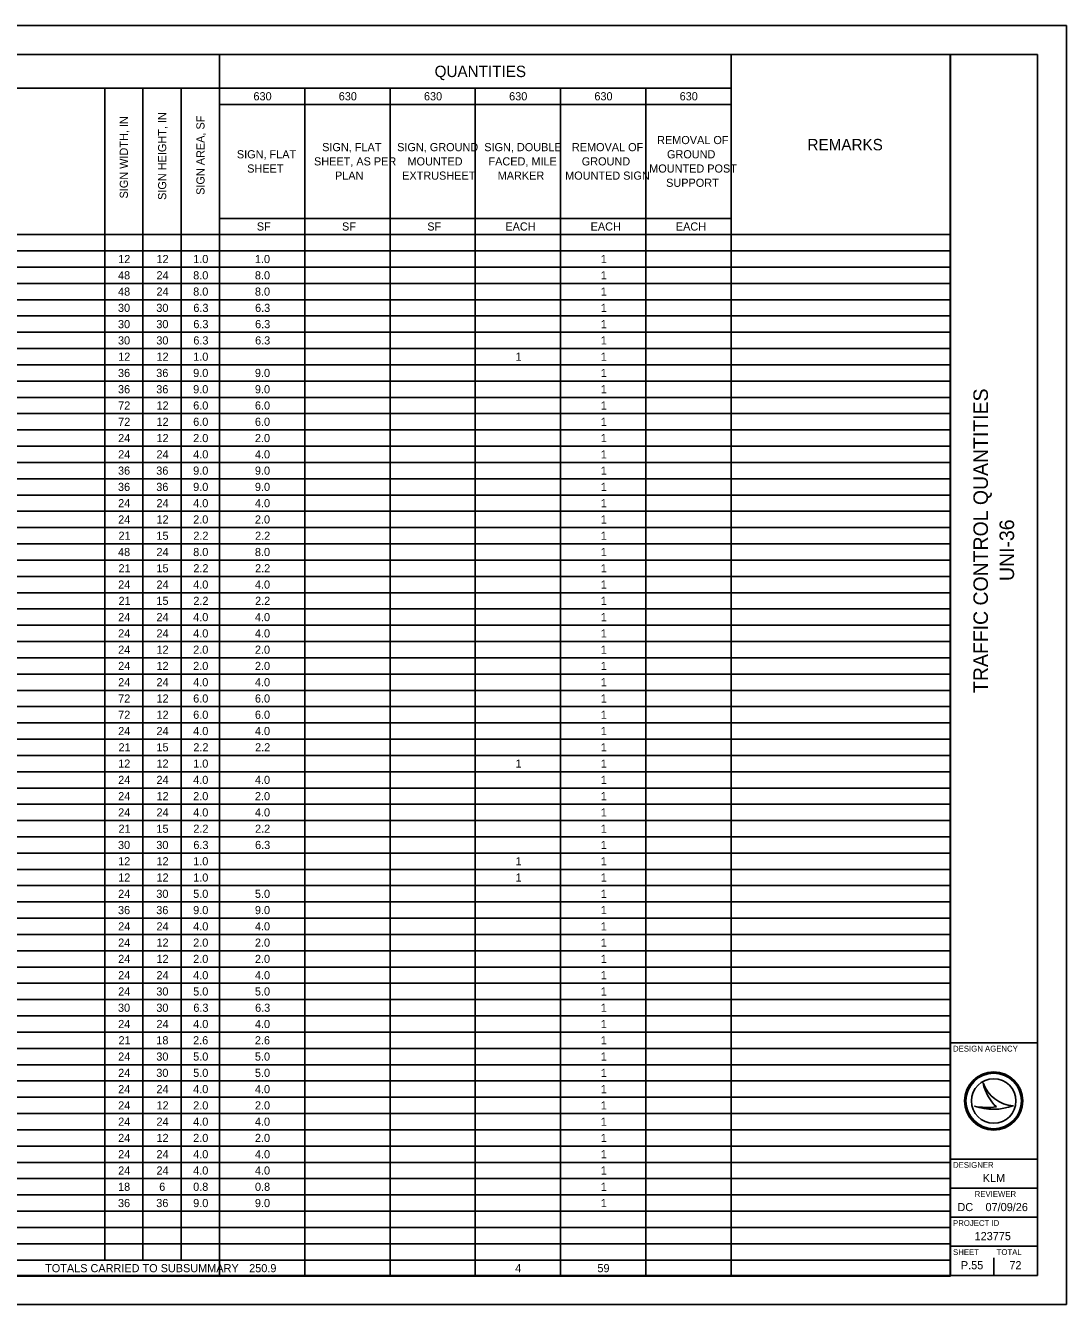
# Model space of a CAD drawing. Extents: x 0 to 34, y 0 to 22.
# Drawn here: x 16.1 to 34, y 0 to 22 of the extents above; entities that cross this region are included whole.
import ezdxf

# ---------------------------------------------------------------- set-up
doc = ezdxf.new("R2010")
doc.units = 0
for name, color, linetype in [('Default', 7, 'Continuous'), ('SH_Border', 7, 'Continuous'), ('SH_Cut_Line', 7, 'Continuous'), ('SH_Data', 7, 'Continuous')]:
    doc.layers.add(name, color=color, linetype=linetype)

msp = doc.modelspace()

# ---------------------------------------------------------------- linework, layer by layer
at = {"layer": 'SH_Border'}
for p, q in [((32, 0.5), (32, 21.5)), ((32, 4.5), (33.5, 4.5)), ((32, 2.5), (33.5, 2.5)), ((32, 2), (33.5, 2)), ((32, 1.5), (33.5, 1.5)), ((32, 1), (33.5, 1))]:
    msp.add_line(p, q, dxfattribs=at)
msp.add_lwpolyline([(1.5, 21.5), (33.5, 21.5), (33.5, 0.5), (1.5, 0.5)], close=True, dxfattribs=at)
at = {"layer": 'SH_Cut_Line'}
msp.add_lwpolyline([(0, 0), (34, 0), (34, 22), (0, 22)], close=True, dxfattribs=at)
at = {"layer": 'SH_Data'}
for p, q in [((1.5, 21.5), (32.004, 21.5)), ((19.436, 21.5), (19.436, 0.484)), ((28.232, 21.5), (28.232, 0.484)), ((32.004, 21.5), (32.004, 0.484)), ((1.5, 20.924), (28.232, 20.924)), ((17.46, 20.924), (17.46, 0.764)), ((18.119, 20.924), (18.119, 0.764)), ((18.778, 20.924), (18.778, 0.764)), ((20.902, 20.924), (20.902, 0.484)), ((22.368, 20.924), (22.368, 0.484)), ((23.834, 20.924), (23.834, 0.484)), ((25.3, 20.924), (25.3, 0.484)), ((26.766, 20.924), (26.766, 0.484)), ((19.436, 20.644), (28.232, 20.644)), ((19.436, 18.684), (28.232, 18.684)), ((1.5, 18.404), (32.004, 18.404)), ((1.5, 18.124), (32.004, 18.124)), ((1.5, 17.844), (32.004, 17.844)), ((1.5, 17.564), (32.004, 17.564)), ((1.5, 17.284), (32.004, 17.284)), ((1.5, 17.004), (32.004, 17.004)), ((1.5, 16.724), (32.004, 16.724)), ((1.5, 16.444), (32.004, 16.444)), ((1.5, 16.164), (32.004, 16.164)), ((1.5, 15.884), (32.004, 15.884)), ((1.5, 15.604), (32.004, 15.604)), ((1.5, 15.324), (32.004, 15.324)), ((1.5, 15.044), (32.004, 15.044)), ((1.5, 14.764), (32.004, 14.764)), ((1.5, 14.484), (32.004, 14.484)), ((1.5, 14.204), (32.004, 14.204)), ((1.5, 13.924), (32.004, 13.924)), ((1.5, 13.644), (32.004, 13.644)), ((1.5, 13.364), (32.004, 13.364)), ((1.5, 13.084), (32.004, 13.084)), ((1.5, 12.804), (32.004, 12.804)), ((1.5, 12.524), (32.004, 12.524)), ((1.5, 12.244), (32.004, 12.244)), ((1.5, 11.964), (32.004, 11.964)), ((1.5, 11.684), (32.004, 11.684)), ((1.5, 11.404), (32.004, 11.404)), ((1.5, 11.124), (32.004, 11.124)), ((1.5, 10.844), (32.004, 10.844)), ((1.5, 10.564), (32.004, 10.564)), ((1.5, 10.284), (32.004, 10.284)), ((1.5, 10.004), (32.004, 10.004)), ((1.5, 9.724), (32.004, 9.724)), ((1.5, 9.444), (32.004, 9.444)), ((1.5, 9.164), (32.004, 9.164)), ((1.5, 8.884), (32.004, 8.884)), ((1.5, 8.604), (32.004, 8.604)), ((1.5, 8.324), (32.004, 8.324)), ((1.5, 8.044), (32.004, 8.044)), ((1.5, 7.764), (32.004, 7.764)), ((1.5, 7.484), (32.004, 7.484)), ((1.5, 7.204), (32.004, 7.204)), ((1.5, 6.924), (32.004, 6.924)), ((1.5, 6.644), (32.004, 6.644)), ((1.5, 6.364), (32.004, 6.364)), ((1.5, 6.084), (32.004, 6.084)), ((1.5, 5.804), (32.004, 5.804)), ((1.5, 5.524), (32.004, 5.524)), ((1.5, 5.244), (32.004, 5.244)), ((1.5, 4.964), (32.004, 4.964)), ((1.5, 4.684), (32.004, 4.684)), ((1.5, 4.404), (32.004, 4.404)), ((1.5, 4.124), (32.004, 4.124)), ((1.5, 3.844), (32.004, 3.844)), ((32.567, 3.81), (32.567, 3.81)), ((1.5, 3.564), (32.004, 3.564)), ((32.417, 3.41), (32.417, 3.41)), ((32.75, 3.5), (32.75, 3.5)), ((33.087, 3.419), (33.087, 3.419)), ((1.5, 3.284), (32.004, 3.284)), ((1.5, 3.004), (32.004, 3.004)), ((1.5, 2.724), (32.004, 2.724)), ((1.5, 2.444), (32.004, 2.444)), ((1.5, 2.164), (32.004, 2.164)), ((1.5, 1.884), (32.004, 1.884)), ((1.5, 1.604), (32.004, 1.604)), ((1.5, 1.324), (32.004, 1.324)), ((1.5, 1.044), (32.004, 1.044)), ((1.5, 0.764), (32.004, 0.764)), ((32.375, 0.675), (32.375, 0.675)), ((32.75, 0.5), (32.75, 0.8)), ((1.5, 0.484), (32.004, 0.484))]:
    msp.add_line(p, q, dxfattribs=at)
for radius in [0.5, 0.477, 0.477, 0.382]:
    msp.add_circle((32.75, 3.5), radius, dxfattribs=at)
for centre, radius, start, end in [((33.116, 3.998), 0.58, 198.9257, 198.9319), ((33.347, 3.97), 0.796, 191.6379, 191.6421), ((33.116, 3.998), 0.58, 198.9319, 267.1657), ((33.347, 3.97), 0.796, 191.6421, 226.0947), ((32.739, 4.37), 1.013, 251.4576, 290.0832), ((32.648, 4.654), 1.266, 259.4964, 259.4995), ((32.739, 4.37), 1.013, 251.4527, 251.4576), ((32.648, 4.654), 1.266, 259.4995, 276.6672)]:
    msp.add_arc(centre, radius, start, end, dxfattribs=at)

# ---------------------------------------------------------------- texts
at = {"layer": 'Default'}
for s, height, p in [('QUANTITIES', 0.196, (23.134, 21.114)), ('630', 0.14, (20.019, 20.714)), ('630', 0.14, (21.485, 20.714)), ('630', 0.14, (22.951, 20.714)), ('630', 0.14, (24.416, 20.714)), ('630', 0.14, (25.882, 20.714)), ('630', 0.14, (27.348, 20.714)), ('REMOVAL OF ', 0.14, (26.961, 19.961)), ('REMARKS', 0.196, (29.547, 19.854)), ('SIGN, FLAT ', 0.14, (19.734, 19.716)), ('SIGN, FLAT ', 0.14, (21.2, 19.839)), ('SIGN, GROUND ', 0.14, (22.49, 19.839)), ('SIGN, DOUBLE ', 0.14, (23.988, 19.839)), ('REMOVAL OF ', 0.14, (25.495, 19.839)), ('GROUND ', 0.14, (27.131, 19.716)), ('SHEET', 0.14, (19.911, 19.471)), ('SHEET, AS PER ', 0.14, (21.06, 19.594)), ('MOUNTED ', 0.14, (22.668, 19.594)), ('FACED, MILE ', 0.14, (24.061, 19.594)), ('GROUND ', 0.14, (25.665, 19.594)), ('MOUNTED POST ', 0.14, (26.825, 19.471)), ('PLAN', 0.14, (21.421, 19.349)), ('EXTRUSHEET', 0.14, (22.576, 19.349)), ('MARKER', 0.14, (24.219, 19.349)), ('MOUNTED SIGN', 0.14, (25.379, 19.349)), ('SUPPORT', 0.14, (27.116, 19.226)), ('SF', 0.14, (20.076, 18.474)), ('SF', 0.14, (21.542, 18.474)), ('SF', 0.14, (23.008, 18.474)), ('EACH', 0.14, (24.351, 18.474)), ('EACH', 0.14, (25.817, 18.474)), ('EACH', 0.14, (27.283, 18.474)), ('12', 0.14, (17.692, 17.914)), ('12', 0.14, (18.351, 17.914)), ('1.0', 0.14, (18.982, 17.914)), ('1.0', 0.14, (20.044, 17.914)), ('1', 0.14, (25.992, 17.914)), ('48', 0.14, (17.69, 17.634)), ('24', 0.14, (18.351, 17.634)), ('8.0', 0.14, (18.982, 17.634)), ('8.0', 0.14, (20.044, 17.634)), ('1', 0.14, (25.992, 17.634)), ('48', 0.14, (17.69, 17.354)), ('24', 0.14, (18.351, 17.354)), ('8.0', 0.14, (18.982, 17.354)), ('8.0', 0.14, (20.044, 17.354)), ('1', 0.14, (25.992, 17.354)), ('30', 0.14, (17.689, 17.074)), ('30', 0.14, (18.348, 17.074)), ('6.3', 0.14, (18.985, 17.074)), ('6.3', 0.14, (20.047, 17.074)), ('1', 0.14, (25.992, 17.074)), ('30', 0.14, (17.689, 16.794)), ('30', 0.14, (18.348, 16.794)), ('6.3', 0.14, (18.985, 16.794)), ('6.3', 0.14, (20.047, 16.794)), ('1', 0.14, (25.992, 16.794)), ('30', 0.14, (17.689, 16.514)), ('30', 0.14, (18.348, 16.514)), ('6.3', 0.14, (18.985, 16.514)), ('6.3', 0.14, (20.047, 16.514)), ('1', 0.14, (25.992, 16.514)), ('12', 0.14, (17.692, 16.234)), ('12', 0.14, (18.351, 16.234)), ('1.0', 0.14, (18.982, 16.234)), ('1', 0.14, (24.526, 16.234)), ('1', 0.14, (25.992, 16.234)), ('36', 0.14, (17.689, 15.954)), ('36', 0.14, (18.347, 15.954)), ('9.0', 0.14, (18.982, 15.954)), ('9.0', 0.14, (20.044, 15.954)), ('1', 0.14, (25.992, 15.954)), ('36', 0.14, (17.689, 15.674)), ('36', 0.14, (18.347, 15.674)), ('9.0', 0.14, (18.982, 15.674)), ('9.0', 0.14, (20.044, 15.674)), ('1', 0.14, (25.992, 15.674)), ('72', 0.14, (17.692, 15.394)), ('12', 0.14, (18.351, 15.394)), ('6.0', 0.14, (18.982, 15.394)), ('6.0', 0.14, (20.044, 15.394)), ('1', 0.14, (25.992, 15.394)), ('72', 0.14, (17.692, 15.114)), ('12', 0.14, (18.351, 15.114)), ('6.0', 0.14, (18.982, 15.114)), ('6.0', 0.14, (20.044, 15.114)), ('1', 0.14, (25.992, 15.114)), ('24', 0.14, (17.692, 14.834)), ('12', 0.14, (18.351, 14.834)), ('2.0', 0.14, (18.982, 14.834)), ('2.0', 0.14, (20.044, 14.834)), ('1', 0.14, (25.992, 14.834)), ('24', 0.14, (17.692, 14.554)), ('24', 0.14, (18.351, 14.554)), ('4.0', 0.14, (18.982, 14.554)), ('4.0', 0.14, (20.044, 14.554)), ('1', 0.14, (25.992, 14.554)), ('36', 0.14, (17.689, 14.274)), ('36', 0.14, (18.347, 14.274)), ('9.0', 0.14, (18.982, 14.274)), ('9.0', 0.14, (20.044, 14.274)), ('1', 0.14, (25.992, 14.274)), ('36', 0.14, (17.689, 13.994)), ('36', 0.14, (18.347, 13.994)), ('9.0', 0.14, (18.982, 13.994)), ('9.0', 0.14, (20.044, 13.994)), ('1', 0.14, (25.992, 13.994)), ('24', 0.14, (17.692, 13.714)), ('24', 0.14, (18.351, 13.714)), ('4.0', 0.14, (18.982, 13.714)), ('4.0', 0.14, (20.044, 13.714)), ('1', 0.14, (25.992, 13.714)), ('24', 0.14, (17.692, 13.434)), ('12', 0.14, (18.351, 13.434)), ('2.0', 0.14, (18.982, 13.434)), ('2.0', 0.14, (20.044, 13.434)), ('1', 0.14, (25.992, 13.434)), ('21', 0.14, (17.698, 13.154)), ('15', 0.14, (18.35, 13.154)), ('2.2', 0.14, (18.985, 13.154)), ('2.2', 0.14, (20.047, 13.154)), ('1', 0.14, (25.992, 13.154)), ('48', 0.14, (17.69, 12.874)), ('24', 0.14, (18.351, 12.874)), ('8.0', 0.14, (18.982, 12.874)), ('8.0', 0.14, (20.044, 12.874)), ('1', 0.14, (25.992, 12.874)), ('21', 0.14, (17.698, 12.594)), ('15', 0.14, (18.35, 12.594)), ('2.2', 0.14, (18.985, 12.594)), ('2.2', 0.14, (20.047, 12.594)), ('1', 0.14, (25.992, 12.594)), ('24', 0.14, (17.692, 12.314)), ('24', 0.14, (18.351, 12.314)), ('4.0', 0.14, (18.982, 12.314)), ('4.0', 0.14, (20.044, 12.314)), ('1', 0.14, (25.992, 12.314)), ('21', 0.14, (17.698, 12.034)), ('15', 0.14, (18.35, 12.034)), ('2.2', 0.14, (18.985, 12.034)), ('2.2', 0.14, (20.047, 12.034)), ('1', 0.14, (25.992, 12.034)), ('24', 0.14, (17.692, 11.754)), ('24', 0.14, (18.351, 11.754)), ('4.0', 0.14, (18.982, 11.754)), ('4.0', 0.14, (20.044, 11.754)), ('1', 0.14, (25.992, 11.754)), ('24', 0.14, (17.692, 11.474)), ('24', 0.14, (18.351, 11.474)), ('4.0', 0.14, (18.982, 11.474)), ('4.0', 0.14, (20.044, 11.474)), ('1', 0.14, (25.992, 11.474)), ('24', 0.14, (17.692, 11.194)), ('12', 0.14, (18.351, 11.194)), ('2.0', 0.14, (18.982, 11.194)), ('2.0', 0.14, (20.044, 11.194)), ('1', 0.14, (25.992, 11.194)), ('24', 0.14, (17.692, 10.914)), ('12', 0.14, (18.351, 10.914)), ('2.0', 0.14, (18.982, 10.914)), ('2.0', 0.14, (20.044, 10.914)), ('1', 0.14, (25.992, 10.914)), ('24', 0.14, (17.692, 10.634)), ('24', 0.14, (18.351, 10.634)), ('4.0', 0.14, (18.982, 10.634)), ('4.0', 0.14, (20.044, 10.634)), ('1', 0.14, (25.992, 10.634)), ('72', 0.14, (17.692, 10.354)), ('12', 0.14, (18.351, 10.354)), ('6.0', 0.14, (18.982, 10.354)), ('6.0', 0.14, (20.044, 10.354)), ('1', 0.14, (25.992, 10.354)), ('72', 0.14, (17.692, 10.074)), ('12', 0.14, (18.351, 10.074)), ('6.0', 0.14, (18.982, 10.074)), ('6.0', 0.14, (20.044, 10.074)), ('1', 0.14, (25.992, 10.074)), ('24', 0.14, (17.692, 9.794)), ('24', 0.14, (18.351, 9.794)), ('4.0', 0.14, (18.982, 9.794)), ('4.0', 0.14, (20.044, 9.794)), ('1', 0.14, (25.992, 9.794)), ('21', 0.14, (17.698, 9.514)), ('15', 0.14, (18.35, 9.514)), ('2.2', 0.14, (18.985, 9.514)), ('2.2', 0.14, (20.047, 9.514)), ('1', 0.14, (25.992, 9.514)), ('12', 0.14, (17.692, 9.234)), ('12', 0.14, (18.351, 9.234)), ('1.0', 0.14, (18.982, 9.234)), ('1', 0.14, (24.526, 9.234)), ('1', 0.14, (25.992, 9.234)), ('24', 0.14, (17.692, 8.954)), ('24', 0.14, (18.351, 8.954)), ('4.0', 0.14, (18.982, 8.954)), ('4.0', 0.14, (20.044, 8.954)), ('1', 0.14, (25.992, 8.954)), ('24', 0.14, (17.692, 8.674)), ('12', 0.14, (18.351, 8.674)), ('2.0', 0.14, (18.982, 8.674)), ('2.0', 0.14, (20.044, 8.674)), ('1', 0.14, (25.992, 8.674)), ('24', 0.14, (17.692, 8.394)), ('24', 0.14, (18.351, 8.394)), ('4.0', 0.14, (18.982, 8.394)), ('4.0', 0.14, (20.044, 8.394)), ('1', 0.14, (25.992, 8.394)), ('21', 0.14, (17.698, 8.114)), ('15', 0.14, (18.35, 8.114)), ('2.2', 0.14, (18.985, 8.114)), ('2.2', 0.14, (20.047, 8.114)), ('1', 0.14, (25.992, 8.114)), ('30', 0.14, (17.689, 7.834)), ('30', 0.14, (18.348, 7.834)), ('6.3', 0.14, (18.985, 7.834)), ('6.3', 0.14, (20.047, 7.834)), ('1', 0.14, (25.992, 7.834)), ('12', 0.14, (17.692, 7.554)), ('12', 0.14, (18.351, 7.554)), ('1.0', 0.14, (18.982, 7.554)), ('1', 0.14, (24.526, 7.554)), ('1', 0.14, (25.992, 7.554)), ('12', 0.14, (17.692, 7.274)), ('12', 0.14, (18.351, 7.274)), ('1.0', 0.14, (18.982, 7.274)), ('1', 0.14, (24.526, 7.274)), ('1', 0.14, (25.992, 7.274)), ('24', 0.14, (17.692, 6.994)), ('30', 0.14, (18.348, 6.994)), ('5.0', 0.14, (18.982, 6.994)), ('5.0', 0.14, (20.044, 6.994)), ('1', 0.14, (25.992, 6.994)), ('36', 0.14, (17.689, 6.714)), ('36', 0.14, (18.347, 6.714)), ('9.0', 0.14, (18.982, 6.714)), ('9.0', 0.14, (20.044, 6.714)), ('1', 0.14, (25.992, 6.714)), ('24', 0.14, (17.692, 6.434)), ('24', 0.14, (18.351, 6.434)), ('4.0', 0.14, (18.982, 6.434)), ('4.0', 0.14, (20.044, 6.434)), ('1', 0.14, (25.992, 6.434)), ('24', 0.14, (17.692, 6.154)), ('12', 0.14, (18.351, 6.154)), ('2.0', 0.14, (18.982, 6.154)), ('2.0', 0.14, (20.044, 6.154)), ('1', 0.14, (25.992, 6.154)), ('24', 0.14, (17.692, 5.874)), ('12', 0.14, (18.351, 5.874)), ('2.0', 0.14, (18.982, 5.874)), ('2.0', 0.14, (20.044, 5.874)), ('1', 0.14, (25.992, 5.874)), ('24', 0.14, (17.692, 5.594)), ('24', 0.14, (18.351, 5.594)), ('4.0', 0.14, (18.982, 5.594)), ('4.0', 0.14, (20.044, 5.594)), ('1', 0.14, (25.992, 5.594)), ('24', 0.14, (17.692, 5.314)), ('30', 0.14, (18.348, 5.314)), ('5.0', 0.14, (18.982, 5.314)), ('5.0', 0.14, (20.044, 5.314)), ('1', 0.14, (25.992, 5.314)), ('30', 0.14, (17.689, 5.034)), ('30', 0.14, (18.348, 5.034)), ('6.3', 0.14, (18.985, 5.034)), ('6.3', 0.14, (20.047, 5.034)), ('1', 0.14, (25.992, 5.034)), ('24', 0.14, (17.692, 4.754)), ('24', 0.14, (18.351, 4.754)), ('4.0', 0.14, (18.982, 4.754)), ('4.0', 0.14, (20.044, 4.754)), ('1', 0.14, (25.992, 4.754)), ('21', 0.14, (17.698, 4.474)), ('18', 0.14, (18.348, 4.474)), ('2.6', 0.14, (18.981, 4.474)), ('2.6', 0.14, (20.043, 4.474)), ('1', 0.14, (25.992, 4.474)), ('24', 0.14, (17.692, 4.194)), ('30', 0.14, (18.348, 4.194)), ('5.0', 0.14, (18.982, 4.194)), ('5.0', 0.14, (20.044, 4.194)), ('1', 0.14, (25.992, 4.194)), ('24', 0.14, (17.692, 3.914)), ('30', 0.14, (18.348, 3.914)), ('5.0', 0.14, (18.982, 3.914)), ('5.0', 0.14, (20.044, 3.914)), ('1', 0.14, (25.992, 3.914)), ('24', 0.14, (17.692, 3.634)), ('24', 0.14, (18.351, 3.634)), ('4.0', 0.14, (18.982, 3.634)), ('4.0', 0.14, (20.044, 3.634)), ('1', 0.14, (25.992, 3.634)), ('24', 0.14, (17.692, 3.354)), ('12', 0.14, (18.351, 3.354)), ('2.0', 0.14, (18.982, 3.354)), ('2.0', 0.14, (20.044, 3.354)), ('1', 0.14, (25.992, 3.354)), ('24', 0.14, (17.692, 3.074)), ('24', 0.14, (18.351, 3.074)), ('4.0', 0.14, (18.982, 3.074)), ('4.0', 0.14, (20.044, 3.074)), ('1', 0.14, (25.992, 3.074)), ('24', 0.14, (17.692, 2.794)), ('12', 0.14, (18.351, 2.794)), ('2.0', 0.14, (18.982, 2.794)), ('2.0', 0.14, (20.044, 2.794)), ('1', 0.14, (25.992, 2.794)), ('24', 0.14, (17.692, 2.514)), ('24', 0.14, (18.351, 2.514)), ('4.0', 0.14, (18.982, 2.514)), ('4.0', 0.14, (20.044, 2.514)), ('1', 0.14, (25.992, 2.514)), ('24', 0.14, (17.692, 2.234)), ('24', 0.14, (18.351, 2.234)), ('4.0', 0.14, (18.982, 2.234)), ('4.0', 0.14, (20.044, 2.234)), ('1', 0.14, (25.992, 2.234)), ('18', 0.14, (17.69, 1.954)), ('6', 0.14, (18.398, 1.954)), ('0.8', 0.14, (18.982, 1.954)), ('0.8', 0.14, (20.045, 1.954)), ('1', 0.14, (25.992, 1.954)), ('36', 0.14, (17.689, 1.674)), ('36', 0.14, (18.347, 1.674)), ('9.0', 0.14, (18.982, 1.674)), ('9.0', 0.14, (20.044, 1.674)), ('1', 0.14, (25.992, 1.674)), ('TOTALS CARRIED TO SUBSUMMARY', 0.14, (16.436, 0.554)), ('250.9', 0.14, (19.945, 0.554)), ('4', 0.14, (24.52, 0.554)), ('59', 0.14, (25.934, 0.554))]:
    msp.add_text(s, height=height, dxfattribs=at).set_placement(p)
for s, p in [('SIGN HEIGHT, IN', (18.518, 19.001)), ('SIGN WIDTH, IN', (17.859, 19.026)), ('SIGN AREA, SF', (19.177, 19.088))]:
    msp.add_text(s, height=0.14, rotation=90, dxfattribs=at).set_placement(p)
at = {"layer": 'SH_Data'}
for s, p in [('TRAFFIC CONTROL QUANTITIES', (32.65, 10.519)), ('UNI-36', (33.1, 12.445))]:
    msp.add_text(s, height=0.25, rotation=90, dxfattribs=at).set_placement(p)
for s, height, p in [('DESIGN AGENCY', 0.1, (32.05, 4.35)), ('DESIGNER', 0.1, (32.05, 2.35)), ('KLM', 0.14, (32.561, 2.105)), ('REVIEWER', 0.1, (32.422, 1.85)), ('DC', 0.14, (32.126, 1.605)), ('07/09/26', 0.14, (32.609, 1.605)), ('PROJECT ID', 0.1, (32.05, 1.35)), ('123775', 0.14, (32.421, 1.105)), ('SHEET', 0.1, (32.05, 0.85)), ('TOTAL', 0.1, (32.8, 0.85)), ('P.55', 0.14, (32.185, 0.605)), ('72', 0.14, (33.019, 0.605))]:
    msp.add_text(s, height=height, dxfattribs=at).set_placement(p)

doc.saveas('drawing.dxf')
